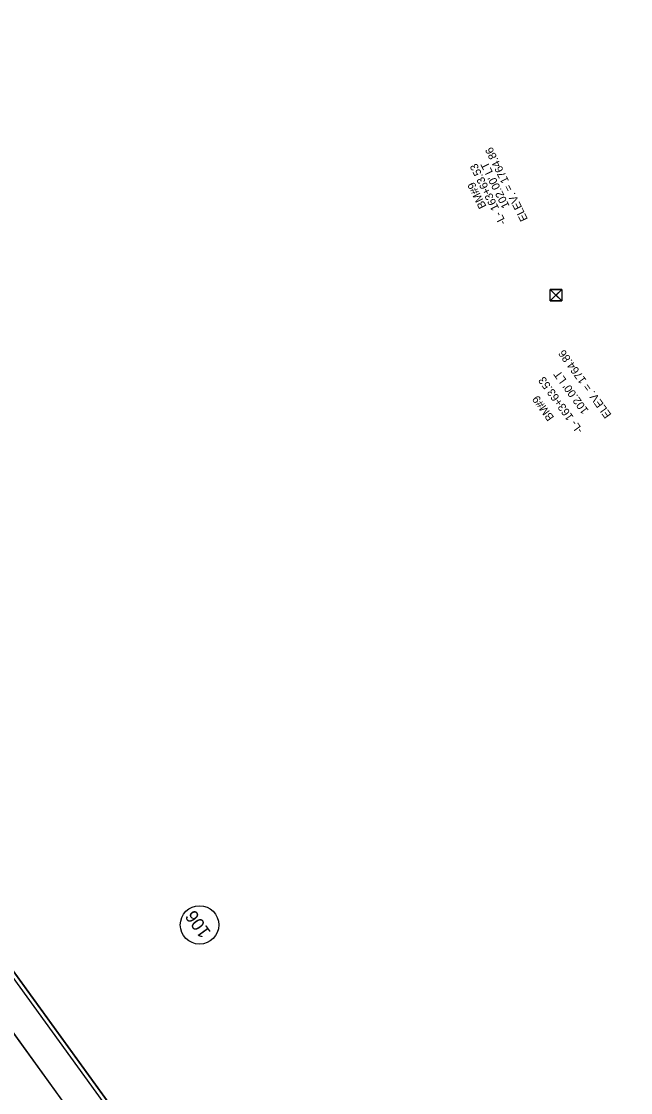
# Model space of a CAD drawing. Extents: x 474925 to 478950, y 494687 to 502905.
# Drawn here: x 475305 to 475686, y 501707 to 502376 of the extents above; entities that cross this region are included whole.
import ezdxf

# ---------------------------------------------------------------- set-up
doc = ezdxf.new("R2010")
doc.units = 0
for name, color, linetype in [('Default', 7, 'Continuous'), ('Prop Parcel Number CELL', 7, 'Continuous'), ('Sheet Cutting Line CELL', 7, 'Continuous'), ('Sheet Layout Plan Border', 7, 'Continuous'), ('Sheet Plan CELL', 7, 'Continuous'), ('Sheet Plan Layout CELL', 7, 'Continuous'), ('Sheet Plot Border Inside CELL', 7, 'Continuous'), ('Sheet Plot Border Outside CELL', 7, 'Continuous')]:
    doc.layers.add(name, color=color, linetype=linetype)

msp = doc.modelspace()

# ---------------------------------------------------------------- linework, layer by layer
at = {"layer": 'Default'}
msp.add_line((475639.42, 502205.4), (475639.42, 502205.4), dxfattribs=at)
msp.add_lwpolyline([(475635.83, 502208.98), (475643.01, 502208.98), (475643.01, 502201.8), (475635.83, 502201.8)], close=True, dxfattribs=at)
for points in [[(475643.01, 502208.98), (475635.83, 502201.8), (475639.42, 502205.39), (475643.01, 502201.8), (475635.83, 502208.98)], [(475639.42, 502205.39), (475643.01, 502208.98), (475635.83, 502208.98), (475639.42, 502205.39)], [(475639.42, 502205.39), (475635.83, 502201.8), (475643.01, 502201.8), (475639.42, 502205.39)]]:
    msp.add_lwpolyline(points, dxfattribs=at)
at = {"layer": 'Prop Parcel Number CELL'}
msp.add_line((475416.74, 501812.09), (475416.74, 501812.09), dxfattribs=at)
msp.add_circle((475416.74, 501812.09), 12, dxfattribs=at)
at = {"layer": 'Sheet Cutting Line CELL'}
msp.add_line((474957.48, 502218.18), (475944.82, 500854.61), dxfattribs=at)
at = {"layer": 'Sheet Layout Plan Border'}
for points in [[(476646.38, 501714.39), (476110.18, 502454.92), (476091.75, 502441.57), (476003.49, 502563.46), (475989.43, 502553.28), (475869.09, 502719.48), (475838.05, 502697.01), (475782.55, 502773.67), (475678.65, 502698.45), (475652.98, 502679.87), (475264.35, 502398.54), (475136.14, 502305.71), (475210.95, 502202.39), (475104.17, 502125.07), (475196.47, 501997.61), (475162.67, 501973.14), (475722, 501200.68)], [(476646.51, 501714.23), (476022.05, 502576.65), (475989.43, 502553.28), (475869.2, 502719.32), (475838.17, 502696.85), (475782.67, 502773.51), (475678.77, 502698.3), (475653.1, 502679.72), (475264.47, 502398.39), (475136.26, 502305.55), (475211.07, 502202.23), (475104.29, 502124.92), (475196.59, 501997.45), (475162.8, 501972.99), (475722.12, 501200.53)]]:
    msp.add_lwpolyline(points, close=True, dxfattribs=at)
at = {"layer": 'Sheet Plan CELL'}
for points in [[(474953.05, 502262.65), (475832.79, 501047.67), (476683.25, 501663.47), (475803.53, 502878.43)], [(476683.28, 501663.49), (475832.82, 501047.66), (475070.38, 502100.6), (475191.92, 502188.6), (475074.61, 502350.64), (475803.53, 502878.43)]]:
    msp.add_lwpolyline(points, close=True, dxfattribs=at)
at = {"layer": 'Sheet Plan Layout CELL'}
msp.add_lwpolyline([(475865.42, 501002.64), (476715.85, 501618.45), (475836.14, 502833.39), (475156.97, 502341.63), (475297.28, 502147.84), (475125.99, 502023.81)], close=True, dxfattribs=at)
at = {"layer": 'Sheet Plot Border Inside CELL'}
msp.add_lwpolyline([(476807.9, 501495.6), (475830.83, 502844.99), (474976.32, 502226.27), (475953.39, 500876.87)], close=True, dxfattribs=at)
at = {"layer": 'Sheet Plot Border Outside CELL'}
msp.add_lwpolyline([(475811.79, 502905.4), (476799.13, 501541.82), (475912.21, 500899.63), (474924.88, 502263.21)], close=True, dxfattribs=at)

# ---------------------------------------------------------------- texts
at = {"layer": 'Default'}
for s, rotation, p in [('ELEV. = 1764.86 ', 116.44074, (475622, 502252.97)), ('-L- 163+63.53', 116.44074, (475608.49, 502250.68)), ("102.00' LT", 116.44074, (475610.63, 502261.1)), ('BM#9', 116.44074, (475596.09, 502260.9)), ('ELEV. = 1764.86 ', 125.90742, (475674.32, 502130.76)), ('-L- 163+63.53', 125.90742, (475656.58, 502121.16)), ("102.00' LT", 125.90742, (475660.08, 502133.38)), ('BM#9', 125.90742, (475638.48, 502129.11))]:
    msp.add_text(s, height=5, rotation=rotation, dxfattribs=at).set_placement(p)
at = {"layer": 'Prop Parcel Number CELL'}
msp.add_text('106', height=8, rotation=125.90742, dxfattribs=at).set_placement((475424.16, 501807.55))

doc.saveas('drawing.dxf')
